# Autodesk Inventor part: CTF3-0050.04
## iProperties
Shininess: 64.0
Length Units: 11269
Angle Units: 11279
Time Units: 11290
Mass Units: 11283
Length Display Precision: 3
Angle Display Precision: 2
Compacted: True
Part Number: CTF3-0050.04
Document SubType Name: Modeling
Created: 2003-11
Designer: Lollo
Density: 0.0
Volumn: 0.0
Area: 0.0
PropertySet Name: Model Information
Control State: 0
Master: False
Checked Out: False
Author: Lollo
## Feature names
1. Estrusione1 [Extrusion]
2. Foro5 [Hole]
